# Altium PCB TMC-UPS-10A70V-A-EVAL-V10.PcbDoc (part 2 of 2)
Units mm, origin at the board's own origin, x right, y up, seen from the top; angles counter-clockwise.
Board outline 85 x 55 mm, 4 copper layers (Top Layer, Mid1, Mid2, Bottom Layer), stack 1.572 mm thick; 131 components, 65 nets, 443 pads, 731 vias.
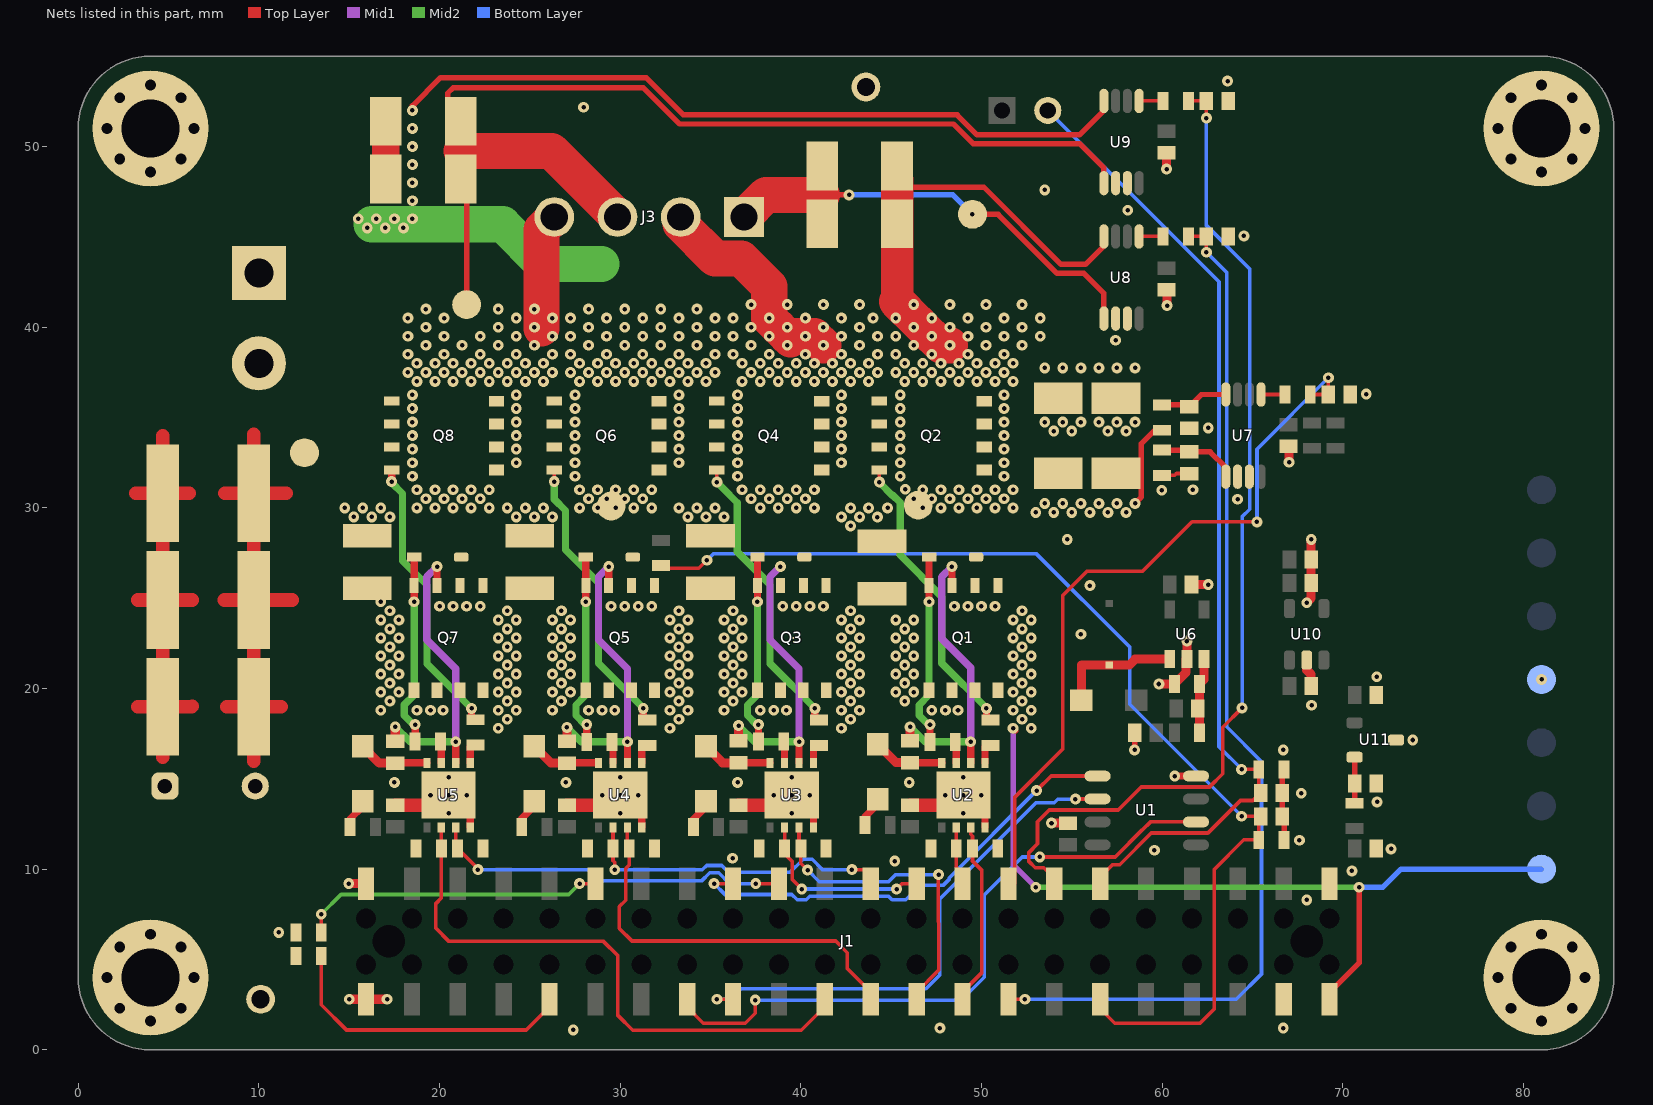
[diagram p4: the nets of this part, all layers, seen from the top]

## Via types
v1: diameter 0.6, hole 0.25, Top Layer to Bottom Layer, tented both sides, 699 vias
v2: diameter 1, hole 0.6, Top Layer to Bottom Layer, tented both sides, 32 vias

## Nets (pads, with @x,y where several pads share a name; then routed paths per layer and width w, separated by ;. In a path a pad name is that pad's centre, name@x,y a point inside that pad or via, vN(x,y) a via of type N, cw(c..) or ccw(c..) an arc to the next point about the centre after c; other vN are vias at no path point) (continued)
GND: C1.1 C2.1 C3.1 C4.1 C5.1 C10.1 C12.1 C13.1 C14.1 C15.1 C16.1 C21.1 C22.1 C23.1 C24.1 C25.1 C26.1 C27.2 C28.1 C29.1 C30.1 C31.1 C32.1 C33.1 C34.1 C35.1 C36.1 J1.2 J1.3 J1.43 J1.44 J2.1 MP1.1 MP2.1 MP3.1 MP4.1 R1.1 R2.1 R3.1 R4.1 R8.1 R9.1 R13.1 R14.1 R18.1 R19.1 R24.1 R25.1 R26.1 R28.1 R31.1 R32.1 TP_GND1.1 TP_GND2.1 TP_GND3.1 U1.4 U2.4 U2.9 U3.4 U3.9 U4.4 U4.9 U5.4 U5.9 U6.2 U7.2 U7.3 U8.2 U8.3 U9.2 U9.3 U10.2 U11.3 | length 72.6
  Top Layer w0.2: R28.1@60,31.8 60.7,31.8 60.8,31.9 C22.1@61.5,31.9
  Top Layer w0.3: v1(20.5,14.1) U5.9@21.7,12.9 ; v1(30,14.1) U4.9@31.2,12.9 ; v1(39.5,14.1) U3.9@40.7,12.9 ; v1(49,14.1) U2.9@50.2,12.9 ; v1(58.475,16.6) C12.1@58.475,17.55 ; R31.1@66.75,11.625 66.75,12.825 C25.1@66.65,12.925 C26.1@66.65,14.225 66.65,15.425 R32.1@66.75,15.525
  Top Layer w0.4: U5.4@21.7,12.315 U5.9@21.7,12.9 ; U4.4@31.2,12.315 U4.9@31.2,12.9 ; U3.4@40.7,12.315 U3.9@40.7,12.9 ; U2.4@50.2,12.315 U2.9@50.2,12.9 ; v1(60.7,15.155) U1.4@61.875,15.155
  Top Layer w0.5: v1(14.975,9.2) J1.44@15.93,9.2 ; v1(15,2.8) v1(17.1,2.8) ; v1(53.875,12.55) C5.1@54.8,12.55 ; v1(59.825,20.25) R24.1@60.675,20.25 61.325,20.9 61.325,21.625 U6.2@61.375,21.625 v1(61.375,22.625) ; C29.1@60.15,49.65 C29.1@60.25,49.65 v1(60.25,48.75) ; v1(60.275,41.2) C27.2@60.275,42.05 ; C10.1@61.625,25.75 v1(62.55,25.75) ; C23.1@67,33.4 67.025,33.375 v1(67.025,32.525) ; U10.2@68,21.575 68,21.025 68.25,20.775 C31.1@68.25,20.15 ; v1(68,24.75) 68.25,25 C32.1@68.25,25.85 C33.1@68.25,27.15 v1(68.25,28.25)
  Top Layer w0.75: 3.175,30.8 C2.1@4.675,30.8 ; 3.3,19 C4.1@4.675,19 ; 3.3,24.9 C3.1@4.675,24.9 ; 4.675,16.2 C4.1@4.675,19 ; 4.675,34 C2.1@4.675,30.8 ; 6.15,30.8 C2.1@4.675,30.8 ; 6.3,19.025 6.275,19 C4.1@4.675,19 ; 6.3,24.9 C3.1@4.675,24.9 ; C16.1@17.55,13.55 19.95,13.55 v1(20.5,14.1) ; C15.1@27.05,13.55 29.45,13.55 v1(30,14.1) ; C14.1@36.55,13.55 38.95,13.55 v1(39.5,14.1) ; C13.1@46.05,13.55 48.45,13.55 v1(49,14.1) ; C4.1@4.675,19 C3.1@4.675,24.9 ; C3.1@4.675,24.9 C2.1@4.675,30.8
  other v1: 27.4,1.1 47.7,1.2 66.7,1.2 11.1,6.5 68,8.3 70.5,9.9 45.2,10.45 36.225,10.6 59.575,11.05 72.675,11.125 67.6,11.6 20.5,13.1 30,13.1 39.5,13.1 49,13.1 71.9,13.725 19.5,14.1 21.5,14.1 29,14.1 31,14.1 38.5,14.1 40.5,14.1 48,14.1 50,14.1 67.7,14.2 17.5,14.8 27,14.8 36.5,14.8 46,14.8 20.5,15.1 30,15.1 39.5,15.1 49,15.1 66.7,16.6 73.875,17.15 68.275,19.075 81,20.5 71.875,20.65 55.5,23 56,25.7 54.75,28.25 64.175,30.475 59.975,30.975 61.7,31 54,34.25 55,34.25 57,34.25 58,34.25 62.55,34.425 53.5,34.75 54.5,34.75 55.5,34.75 56.5,34.75 57.5,34.75 58.5,34.75 71.3,36.3 53.5,37.75 54.5,37.75 55.5,37.75 56.5,37.75 57.5,37.75 58.5,37.75 57.425,39.275 64.525,45.05 58.1,46.475 53.5,47.6 27.975,52.175 63.625,53.625
  other v2: 4,1.6 81,1.6 2.303,2.303 5.697,2.303 79.303,2.303 82.697,2.303 1.6,4 6.4,4 78.6,4 83.4,4 2.303,5.697 5.697,5.697 79.303,5.697 82.697,5.697 4,6.4 81,6.4 4,48.6 81,48.6 2.303,49.303 5.697,49.303 79.303,49.303 82.697,49.303 1.6,51 6.4,51 78.6,51 83.4,51 2.303,52.697 5.697,52.697 79.303,52.697 82.697,52.697 4,53.4 81,53.4
I_SUM: C17.1 C18.1 C19.1 C20.1 Q2.1 Q2.2 Q2.3 Q4.1 Q4.2 Q4.3 Q6.1 Q6.2 Q6.3 Q8.1 Q8.2 Q8.3 R25.2 R26.2 R27.1 | length 4.9
  Top Layer w0.3: v1(58.5,30.25) 58.85,30.6 58.85,33.55 59.6,34.3 R27.1@60,34.3
  other v1: 42.75,29 44.242,29.492 15.25,29.5 16.25,29.5 17.25,29.5 24.25,29.5 25.25,29.5 26.25,29.5 33.75,29.5 34.75,29.5 35.75,29.5 42.25,29.5 43.25,29.5 53,29.75 54,29.75 55,29.75 56,29.75 57,29.75 58,29.75 14.75,30 15.75,30 16.75,30 23.75,30 24.75,30 25.75,30 33.25,30 34.25,30 35.25,30 42.75,30 43.75,30 44.8,30 53.5,30.25 54.5,30.25 55.5,30.25 56.5,30.25 57.5,30.25
NetC6_1: C6.1 D1.1 U2.8 | length 4
  Top Layer w0.4: C6.1@46.05,15.9 46.065,15.885 U2.8@47.8,15.885
  Top Layer w0.5: D1.1@44.25,16.925 45.275,15.9 C6.1@46.05,15.9
NetC6_2: C6.2 D6.2 Q1.1 Q1.2 Q1.3 Q2.5 Q2.6 Q2.7 Q2.8 Q2.9 R35.2 R36.2 TP6.1 U2.6 U8.8 | length 43.1
  Top Layer w0.3: R36.2@45.325,48.925 45.325,48.175 45.75,47.75 50.125,47.75 54.4,43.475 55.75,43.475 56.775,44.5 U8.8@56.775,45.025
  Top Layer w0.4: Q1.3@48.365,25.7 v1(48.365,26.75) ; U2.6@49.4,15.885 v1(49.4,17.05)
  Top Layer w0.5: C6.2@46.05,17.1 v1(46.05,17.875)
  Top Layer w1.8: 45.325,41.425 R35.2@45.325,45.725 R36.2@45.325,48.175
  Top Layer w2: 45.325,41.425 46.5,40.25 v1(47.25,39.5) 47.75,39 v1(48.25,39)
  Mid1 w0.4: v1(48.365,26.75) 47.795,26.18 47.795,22.75 49.4,21.145 v1(49.4,17.05)
  Mid2 w0.4: v1(46.05,17.875) 46.875,17.05 v1(49.4,17.05)
  other v1: 46.75,30 47.75,30 48.75,30 49.75,30 50.75,30 51.75,30 46.25,30.5 47.25,30.5 48.25,30.5 49.25,30.5 50.25,30.5 51.25,30.5 46.75,31 47.75,31 48.75,31 49.75,31 50.75,31 51.75,31 45.777,31.027 45.5,31.75 51.25,31.75 45.5,32.5 51.25,32.5 45.5,33.25 51.25,33.25 45.5,34 51.25,34 45.5,34.75 51.25,34.75 45.5,35.5 51.25,35.5 45.5,36.25 51.25,36.25 45.75,37 46.75,37 47.75,37 48.75,37 49.75,37 50.75,37 51.75,37 45.25,37.5 46.25,37.5 47.25,37.5 48.25,37.5 49.25,37.5 50.25,37.5 51.25,37.5 45.75,38 46.75,38 47.75,38 48.75,38 49.75,38 50.75,38 51.75,38 45.25,38.5 47.25,38.5 49.25,38.5 51.25,38.5 46.25,39 50.25,39 52.25,39 45.25,39.5 49.25,39.5 51.25,39.5 53.25,39.5 46.25,40 48.25,40 50.25,40 52.25,40 45.25,40.5 47.25,40.5 49.25,40.5 51.25,40.5 53.25,40.5 46.25,41.25 48.25,41.25 50.25,41.25 52.25,41.25
NetC7_1: C7.1 D2.1 U3.8 | length 3.9
  Top Layer w0.4: C7.1@36.565,15.885 U3.8@38.3,15.885
  Top Layer w0.5: D2.1@34.75,16.8 35.665,15.885 C7.1@36.565,15.885
NetC7_2: C7.2 D7.2 J3.2 Q3.1 Q3.2 Q3.3 Q4.5 Q4.6 Q4.7 Q4.8 Q4.9 U3.6 | length 28.7
  Top Layer w0.4: U3.6@39.9,15.885 v1(39.9,17.05)
  Top Layer w0.5: C7.2@36.55,17.1 v1(36.55,17.95)
  Top Layer w2: J3.2@33.35,46.1 33.35,45.703 35.253,43.8 36.7,43.8 38.25,42.25 v1(38.25,40.5) 38.75,40 39.25,39.5 39.6,39.5 ; 39.425,39.325 39.6,39.5 ; v1(41.25,39) 40.75,39.5 v1(40.25,39.5) 39.6,39.5
  Mid1 w0.4: v1(38.865,26.75) 38.295,26.18 38.295,22.7 39.9,21.095 v1(39.9,17.05)
  Mid2 w0.4: v1(36.55,17.95) 37.45,17.05 v1(39.9,17.05)
  other v1: 37.75,30 38.75,30 39.75,30 40.75,30 37.25,30.5 38.25,30.5 39.25,30.5 40.25,30.5 36.75,31 37.75,31 38.75,31 39.75,31 40.75,31 36.5,31.75 36.5,32.5 42.25,32.5 36.5,33.25 42.25,33.25 36.5,34 42.25,34 36.5,34.75 42.25,34.75 36.5,35.5 42.25,35.5 36.5,36.25 42.25,36.25 36.75,37 37.75,37 38.75,37 39.75,37 40.75,37 41.75,37 42.75,37 43.75,37 37.25,37.5 38.25,37.5 39.25,37.5 40.25,37.5 41.25,37.5 42.25,37.5 43.25,37.5 44.25,37.5 36.75,38 37.75,38 38.75,38 39.75,38 40.75,38 41.75,38 42.75,38 43.75,38 36.25,38.5 38.25,38.5 40.25,38.5 42.25,38.5 44.25,38.5 37.25,39 39.25,39 43.25,39 36.25,39.5 38.25,39.5 42.25,39.5 44.25,39.5 37.25,40 39.25,40 41.25,40 43.25,40 36.25,40.5 40.25,40.5 42.25,40.5 44,40.5 37.25,41.25 39.25,41.25 41.25,41.25 43.25,41.25
NetC8_1: C8.1 D3.1 U4.8 | length 3.9
  Top Layer w0.2: C8.1@27.05,15.875 C8.1@27.06,15.885
  Top Layer w0.4: C8.1@27.06,15.885 U4.8@28.8,15.885
  Top Layer w0.5: D3.1@25.25,16.8 26.175,15.875 C8.1@27.05,15.875
NetC8_2: C8.2 D8.2 Q5.1 Q5.2 Q5.3 Q6.5 Q6.6 Q6.7 Q6.8 Q6.9 R37.2 R38.2 TP8.1 U4.6 U9.8 | length 75.7
  Top Layer w0.3: v1(18.5,52) 18.5,52.25 20.062,53.812 31.438,53.812 33.5,51.75 48.657,51.75 49.757,50.65 55.425,50.65 56.775,52 U9.8@56.775,52.525
  Top Layer w0.4: Q5.3@29.365,25.7 v1(29.365,26.75) ; U4.6@30.4,15.885 v1(30.4,17.05)
  Top Layer w0.5: C8.2@27.05,17.075 v1(27.05,17.85)
  Top Layer w1.5: R37.2@17.025,48.2 R38.2@17.025,51.4
  Mid1 w0.4: v1(29.365,26.75) 28.795,26.18 28.795,22.7 30.4,21.095 v1(30.4,17.05)
  Mid2 w0.4: v1(27.05,17.85) 27.85,17.05 v1(30.4,17.05)
  Mid2 w2: 16.25,45.7 23.497,45.7 25.697,43.5 28.975,43.5
  other v1: 27.75,30 28.75,30 29.75,30 30.75,30 31.75,30 28.25,30.5 29.25,30.5 30.25,30.5 31.25,30.5 27.75,31 28.75,31 29.75,31 30.75,31 31.75,31 27.5,31.75 27.5,32.5 33.25,32.5 27.5,33.25 33.25,33.25 27.5,34 33.25,34 27.5,34.75 33.25,34.75 27.5,35.5 33.25,35.5 27.5,36.25 33.25,36.25 27.75,37 28.75,37 29.75,37 30.75,37 31.75,37 32.75,37 33.75,37 34.75,37 27.25,37.5 28.25,37.5 29.25,37.5 30.25,37.5 31.25,37.5 32.25,37.5 33.25,37.5 34.25,37.5 35.25,37.5 27.75,38 28.75,38 29.75,38 30.75,38 31.75,38 32.75,38 33.75,38 34.75,38 27.25,38.5 29.25,38.5 31.25,38.5 33.25,38.5 35.25,38.5 28.25,39 30.25,39 32.25,39 34.25,39 27.25,39.5 29.25,39.5 31.25,39.5 33.25,39.5 35.25,39.5 28.25,40 30.25,40 32.25,40 34.25,40 27.25,40.5 29.25,40.5 31.25,40.5 33.25,40.5 35.25,40.5 28.25,41 30.25,41 32.25,41 34.25,41 16,45.5 17,45.5 18,45.5 15.5,46 16.5,46 17.5,46 18.5,46 18.5,47 18.5,48 18.5,49 18.5,50 18.5,51
NetC9_1: C9.1 D4.1 U5.8 | length 3.9
  Top Layer w0.4: C9.1@17.55,15.875 17.56,15.885 U5.8@19.3,15.885
  Top Layer w0.5: D4.1@15.75,16.8 16.675,15.875 C9.1@17.55,15.875
NetC9_2: C9.2 D9.2 J3.4 Q7.1 Q7.2 Q7.3 Q8.5 Q8.6 Q8.7 Q8.8 Q8.9 U5.6 | length 23.8
  Top Layer w0.4: Q7.3@19.865,25.7 v1(19.865,26.75) ; U5.6@20.9,15.885 v1(20.9,17.05)
  Top Layer w0.5: C9.2@17.55,17.075 v1(17.55,17.875)
  Top Layer w2: 25.65,39.925 25.65,40.5 25.65,45.4 J3.4@26.35,46.1
  Mid1 w0.4: v1(19.865,26.75) 19.295,26.18 19.295,22.7 20.9,21.095 v1(20.9,17.05)
  Mid2 w0.4: v1(17.55,17.875) 18.375,17.05 v1(20.9,17.05)
  other v1: 18.75,30 19.75,30 20.75,30 21.75,30 22.75,30 19.25,30.5 20.25,30.5 21.25,30.5 22.25,30.5 18.75,31 19.75,31 20.75,31 21.75,31 22.75,31 18.5,31.75 18.5,32.5 24.25,32.5 18.5,33.25 24.25,33.25 18.5,34 24.25,34 18.5,34.75 24.25,34.75 18.5,35.5 24.25,35.5 18.5,36.25 24.25,36.25 18.75,37 19.75,37 20.75,37 21.75,37 22.75,37 23.75,37 24.75,37 25.75,37 18.25,37.5 19.25,37.5 20.25,37.5 21.25,37.5 22.25,37.5 23.25,37.5 24.25,37.5 25.25,37.5 26.25,37.5 18.75,38 19.75,38 20.75,38 21.75,38 22.75,38 23.75,38 24.75,38 25.75,38 18.25,38.5 20.25,38.5 22.25,38.5 24.25,38.5 26.25,38.5 19.25,39 21.25,39 23.25,39 25.25,39 18.25,39.5 20.25,39.5 22.25,39.5 24.25,39.5 26.25,39.5 19.25,40 23.25,40 25.25,40 18.25,40.5 20.25,40.5 24.25,40.5 26.25,40.5 19.25,41 23.25,41 25.25,41
NetC11_1: C11.1 R23.1 R24.2 U6.3 | length 4.2
  Top Layer w0.5: R23.1@62.075,17.55 R24.2@62.075,20.25 62.325,20.5 U6.3@62.325,21.625
NetC21_2: C21.2 R27.2 U7.8 | length 3.8
  Top Layer w0.2: C21.2@61.4,35.7 C21.2@61.5,35.6
  Top Layer w0.3: R27.2@60,35.7 C21.2@61.4,35.7 ; C21.2@61.5,35.6 62.175,36.275 U7.8@63.525,36.275
NetC22_2: C22.2 R28.2 U7.1 | length 4.4
  Top Layer w0.2: C22.2@61.4,33.2 C22.2@61.5,33.1
  Top Layer w0.3: R28.2@60,33.2 C22.2@61.4,33.2 ; C22.2@61.5,33.1 62.655,33.1 63.525,32.23 U7.1@63.525,31.725
NetC24_2: C24.2 J1.16 R29.2 | length 41
  Top Layer w0.2: J1.16@51.85,9.2 51.85,13.999 54.5,16.649 54.5,25.15 55.85,26.5 58.933,26.5 61.658,29.225 v1(65.25,29.225) ; R29.2@68.2,36.275 C24.2@69.2,36.275 v1(69.2,37.2)
  Bottom Layer w0.2: v1(65.25,29.225) 65.25,33.25 v1(69.2,37.2)
NetC25_2: C25.2 J1.11 R30.1 R31.2 | length 61.2
  Top Layer w0.2: R30.1@32.25,26.8 32.4,26.65 34.35,26.65 v1(34.8,27.1) ; J1.11@56.57,2.8 56.57,2.28 57.375,1.475 62.1,1.475 62.875,2.25 62.875,9.975 64.525,11.625 R31.2@65.35,11.625 65.35,12.825 C25.2@65.45,12.925 v1(64.4,12.925)
  Bottom Layer w0.2: v1(34.8,27.1) 35.15,27.45 53.05,27.45 58.2,22.3 58.2,19.125 v1(64.4,12.925)
NetC26_2: C26.2 J1.12 J4.2 R32.2 | length 54.4
  Top Layer w0.2: J1.12@56.57,9.2 56.57,9.57 57.25,10.25 57.65,10.25 59.4,12 62.534,12 64.334,13.8 65.025,13.8 C26.2@65.45,14.225 65.35,14.325 R32.2@65.35,15.525 v1(64.4,15.525)
  Bottom Layer w0.2: J4.2@53.67,52 63.15,42.52 63.15,16.775 v1(64.4,15.525)
NetC28_2: C28.2 J1.15 R39.2 | length 57.7
  Top Layer w0.2: J1.15@51.49,2.8 v1(52.4,2.8) ; R39.2@61.45,45.025 C28.2@62.45,45.025 v1(62.45,44.15)
  Bottom Layer w0.2: v1(52.4,2.8) 64.1,2.8 65.5,4.2 65.5,15.95 63.575,17.875 63.575,43.025 v1(62.45,44.15)
NetC30_2: C30.2 J1.14 R40.2 | length 55.7
  Top Layer w0.2: J1.14@54.03,9.2 54.03,9.495 53.45,10.075 52.976,10.075 52.625,10.426 52.625,10.924 53.1,11.399 53.1,12.624 53.751,13.275 57.575,13.275 58.85,14.55 62.625,14.55 63.35,15.275 63.35,17.85 v1(64.425,18.925) ; R40.2@61.45,52.525 C30.2@62.45,52.525 v1(62.45,51.575)
  Bottom Layer w0.2: v1(62.45,51.575) 62.45,45.625 64.85,43.225 64.85,29.925 64.425,29.5 v1(64.425,18.925)
NetC35_2: C35.2 R41.1 U11.2 | length 2.6
  Top Layer w0.3: R41.1@70.65,13.65 C35.2@70.65,14.75 U11.2@70.65,16.2
NetD1_2: D1.2 R5.2 | length 1.7
  Top Layer w0.4: R5.2@43.55,12.45 43.55,12.9 44.25,13.6 D1.2@44.25,13.875
NetD2_2: D2.2 R10.2 | length 1.7
  Top Layer w0.2: D2.2@34.75,13.45 D2.2@34.75,13.75
  Top Layer w0.4: R10.2@34.05,12.325 34.05,12.75 D2.2@34.75,13.45
NetD3_2: D3.2 R15.2 | length 1.7
  Top Layer w0.4: R15.2@24.55,12.325 24.55,12.8 25.275,13.525 D3.2@25.275,13.75
NetD4_2: D4.2 R20.2 | length 1.7
  Top Layer w0.4: R20.2@15.05,12.325 15.05,12.775 15.75,13.475 D4.2@15.75,13.75
NetD5_2: D5.2 L1.2 U6.1 | length 7
  Top Layer w0.5: D5.2@55.525,19.35 55.525,21.275 55.55,21.3 L1.2@57.075,21.3 58.175,21.3 58.5,21.625 U6.1@60.425,21.625
NetD6_1: D6.1 Q1.4 R6.2 | length 10.8
  Top Layer w0.4: v1(47.095,24.8) Q1.4@47.095,25.7 D6.1@47.095,27.275 ; R6.2@47.15,17.05 v1(47.15,18)
  Mid2 w0.4: v1(47.095,24.8) 47.095,19.635 46.55,19.09 46.55,18.51 47.06,18 v1(47.15,18)
NetD7_1: D7.1 Q3.4 R11.2 | length 10.5
  Top Layer w0.2: 37.595,26.97 37.6,26.975
  Top Layer w0.4: v1(37.595,24.8) Q3.4@37.595,25.7 37.595,26.97 ; R11.2@37.65,17.075 v1(37.65,18)
  Mid2 w0.4: v1@37.585,17.975 v1@37.625,17.975 ; v1(37.595,24.8) 37.595,19.635 37.05,19.09 37.05,18.51 37.56,18 v1(37.65,18)
NetD8_1: D8.1 Q5.4 R16.2 | length 10.7
  Top Layer w0.4: v1(28.095,24.8) Q5.4@28.095,25.7 D8.1@28.095,27.225 ; R16.2@28.15,17.05 v1(28.15,18)
  Mid2 w0.4: v1(28.095,24.8) 28.095,19.645 27.825,19.375 27.825,19.365 27.55,19.09 27.55,18.51 28.06,18 v1(28.15,18)
NetD9_1: D9.1 Q7.4 R21.2 | length 10.4
  Top Layer w0.4: v1(18.595,24.8) Q7.4@18.595,25.7 18.595,26.97 18.6,26.975 ; R21.2@18.65,17.075 v1(18.65,18)
  Mid2 w0.4: v1(18.595,24.8) 18.595,19.645 18.05,19.1 18.05,18.51 18.56,18 v1(18.65,18)
NetJ1_17: J1.17 R4.2 U2.3 | length 10.2
  Top Layer w0.2: J1.17@48.95,2.8 48.95,3.2 50.025,4.275 50.025,9.925 49.5,10.45 R4.2@49.5,11.15 49.5,11.825 49.4,11.925 U2.3@49.4,12.315
NetJ1_18: J1.18 R3.2 U2.2 | length 3.3
  Top Layer w0.2: U2.2@48.6,12.315 R3.2@48.6,11.15 48.6,10.1 48.95,9.75 J1.18@48.95,9.2
NetJ1_19: J1.19 R9.2 U3.3 | length 17.6
  Top Layer w0.2: U3.3@39.9,12.315 39.9,11.25 R9.2@40,11.15 40,10.327 v1(40.377,9.95) ; J1.19@46.41,2.8 46.41,3.185 47.625,4.4 v1@47.6,9.7
  Bottom Layer w0.2: v1(40.377,9.95) 41.027,9.3 44.851,9.3 45.251,9.7 v1(47.625,9.7)
NetJ1_20: J1.20 R8.2 U3.2 | length 10.3
  Top Layer w0.2: U3.2@39.1,12.315 R8.2@39.1,11.15 39.1,10.85 39.525,10.425 39.525,9.425 v1(40.05,8.9) ; v1(45.3,8.9) 45.6,9.2 J1.20@46.41,9.2
  Bottom Layer w0.2: v1(40.05,8.9) v1(45.3,8.9)
NetJ1_21: J1.21 R14.2 U4.3 | length 22.4
  Top Layer w0.2: U4.3@30.4,12.315 30.4,11.25 R14.2@30.5,11.15 ; R14.2@30.675,10.975 R14.2@30.5,11.15 ; J1.21@43.87,2.8 43.87,3.205 42.575,4.5 42.575,5.375 41.925,6.025 30.65,6.025 29.955,6.72 29.955,7.93 30.3,8.275 30.3,10.034 30.5,10.234 R14.2@30.5,11.15
NetJ1_22: J1.22 R13.2 U4.2 | length 17.9
  Top Layer w0.2: U4.2@29.6,12.315 R13.2@29.6,11.15 29.6,10.475 29.7,10.375 v1(29.7,9.965) ; v1(42.825,9.975) 43.45,9.975 43.87,9.555 J1.22@43.87,9.2
  Bottom Layer w0.2: v1(29.7,9.965) 34.551,9.965 34.786,10.2 35.614,10.2 35.989,9.825 39.403,9.825 40.128,10.55 40.625,10.55 41.201,9.975 v1(42.825,9.975)
NetJ1_23: J1.23 R18.2 U5.2 | length 32.5
  Top Layer w0.2: U5.2@20.1,12.315 R18.2@20.1,11.15 20.1,8.4 19.8,8.1 19.8,6.725 20.525,6 29.075,6 29.875,5.2 29.875,1.9 30.7,1.075 40.025,1.075 41.33,2.38 J1.23@41.33,2.8
NetJ1_26: J1.26 R19.2 U5.3 | length 20.2
  Top Layer w0.2: U5.3@20.9,12.315 20.9,11.25 R19.2@21,11.15 22.125,10.025 v1(22.125,9.975) ; v1(37.5,9.2) J1.26@38.79,9.2
  Bottom Layer w0.2: v1(22.125,9.975) 28.25,9.975 28.875,9.35 34.501,9.35 34.951,9.8 35.449,9.8 36.049,9.2 v1(37.5,9.2)
NetJ3_1: J3.1 R35.1 R36.1 TP7.1 U8.1 | length 24.1
  Top Layer w0.3: 41.175,47.325 v1(42.675,47.325) ; v1(49.5,46.25) 50.918,46.25 54.193,42.975 55.675,42.975 56.775,41.875 U8.1@56.775,40.475
  Top Layer w2: J3.1@36.85,46.1 38.075,47.325 41.175,47.325
  Bottom Layer w0.3: v1(42.675,47.325) 48.425,47.325 v1(49.5,46.25)
NetJ3_3: J3.3 R37.1 R38.1 TP9.1 U9.1 | length 58.7
  Top Layer w0.3: R38.1@20.45,52.6 20.45,52.95 20.75,53.25 31.293,53.25 33.293,51.25 48.45,51.25 49.55,50.15 55.45,50.15 56.775,48.825 U9.1@56.775,47.975 ; R38.1@21.175,51.4 R38.1@21.175,51.825 ; 21.225,49.75 21.5,49.475 TP9.1@21.5,41.25
  Top Layer w2: 21.225,49.75 26.2,49.75 J3.3@29.85,46.1
NetQ2_4: Q2.4 R7.2 | length 16.3
  Top Layer w0.2: v1(44.35,31.425) Q2.4@44.35,32.095
  Top Layer w0.4: R7.2@50.275,18.25 v1(50.275,18.9)
  Mid2 w0.4: v1(44.35,31.425) 44.35,31.4 45.05,30.7 45.09,30.7 45.5,30.29 45.5,27.385 47.8,25.085 47.8,21.4 v1@50.275,18.925
NetQ4_4: Q4.4 R12.2 | length 16.1
  Top Layer w0.2: v1(35.35,31.425) Q4.4@35.35,32.095
  Top Layer w0.4: R12.2@40.775,18.25 v1(40.775,18.9)
  Mid2 w0.4: v1(35.35,31.425) 36.05,30.725 36.05,30.71 36.46,30.3 36.475,30.3 36.475,27.575 38.3,25.75 38.3,21.375 v1@40.75,18.925
NetQ6_4: Q6.4 R17.2 | length 15.9
  Top Layer w0.2: v1(26.35,31.45) Q6.4@26.35,32.095
  Top Layer w0.4: R17.2@31.275,18.25 v1(31.275,18.9)
  Mid2 w0.4: v1(26.35,31.45) 26.35,30.475 26.975,29.85 26.975,27.675 28.8,25.85 28.8,21.4 v1@31.275,18.925
NetQ8_4: Q8.4 R22.2 | length 15.7
  Top Layer w0.4: v1(17.35,31.45) Q8.4@17.35,32.095 ; R22.2@21.775,18.25 v1(21.775,18.9)
  Mid2 w0.4: v1(17.35,31.45) 17.35,31.39 17.95,30.79 17.95,27.075 19.3,25.725 19.3,21.375 v1(21.775,18.9)
NetR6_1: R6.1 U2.7 | length 1.2
  Top Layer w0.4: R6.1@48.55,17.05 48.6,17 U2.7@48.6,15.885
NetR7_1: R7.1 U2.5 | length 1
  Top Layer w0.3: R7.1@50.2,16.775 R7.1@50.275,16.85
  Top Layer w0.4: U2.5@50.2,15.885 R7.1@50.2,16.775
NetR11_1: R11.1 U3.7 | length 1.1
  Top Layer w0.4: U3.7@39.1,15.885 R11.1@39.1,17.025
NetR12_1: R12.1 U3.5 | length 1
  Top Layer w0.3: R12.1@40.7,16.775 R12.1@40.775,16.85
  Top Layer w0.4: U3.5@40.7,15.885 R12.1@40.7,16.775
NetR16_1: R16.1 U4.7 | length 0.8
  Top Layer w0.4: U4.7@29.6,15.885 R16.1@29.6,16.7
NetR17_1: R17.1 U4.5 | length 1
  Top Layer w0.3: R17.1@31.2,16.775 R17.1@31.275,16.85
  Top Layer w0.4: U4.5@31.2,15.885 R17.1@31.2,16.775
NetR21_1: R21.1 U5.7 | length 1.2
  Top Layer w0.4: U5.7@20.1,15.885 R21.1@20.1,17.075
NetR22_1: R22.1 U5.5 | length 1
  Top Layer w0.3: R22.1@21.7,16.775 R22.1@21.775,16.85
  Top Layer w0.4: U5.5@21.7,15.885 R22.1@21.7,16.775
NetR29_1: R29.1 U7.5 | length 1.3
  Top Layer w0.2: U7.5@65.475,36.275 R29.1@66.8,36.275
NetR39_1: R39.1 U8.5 | length 1.3
  Top Layer w0.2: U8.5@58.725,45.025 R39.1@60.05,45.025
NetR40_1: R40.1 U9.5 | length 1.3
  Top Layer w0.2: U9.5@58.725,52.525 R40.1@60.05,52.525
PWM_H_IDLE: J1.34 R2.2 | length 16.9
  Top Layer w0.2: R2.2@13.45,6.5 v1(13.45,7.5) ; v1(27.75,9.2) J1.34@28.63,9.2
  Mid2 w0.2: v1(13.45,7.5) 14.55,8.6 27.15,8.6 v1(27.75,9.2)
PWM_L_IDLE: J1.35 R1.2 | length 16.9
  Top Layer w0.2: R1.2@13.45,5.2 13.45,2.5 14.85,1.1 24.8,1.1 26.09,2.39 J1.35@26.09,2.8
SPI2_SCK: J1.27 U1.6 | length 29
  Top Layer w0.2: v1(35.35,2.8) J1.27@36.25,2.8 ; v1@55.2,13.885 U1.6@56.425,13.885
  Bottom Layer w0.2: v1(35.35,2.8) 36.125,2.8 36.7,3.375 46.925,3.375 47.7,4.15 47.7,8.361 53.014,13.675 54.025,13.675 54.225,13.875 v1(55.2,13.875)
SPI2_SDI: J1.29 U1.2 | length 36.4
  Top Layer w0.2: J1.29@33.71,2.8 33.71,2.365 34.6,1.475 36.925,1.475 37.475,2.025 v1@37.475,2.475 ; v1(53.225,10.675) 57.4,10.675 58.89,12.165 58.901,12.165 59.351,12.615 U1.2@61.875,12.615
  Bottom Layer w0.2: v1(37.475,2.75) 48.875,2.75 50.15,4.025 50.15,8.575 52.25,10.675 v1(53.225,10.675)
SPI2_SDO: J1.28 U1.5 | length 25.7
  Top Layer w0.2: v1(35.2,9.2) J1.28@36.25,9.2 ; v1(53.05,14.35) 53.855,15.155 U1.5@56.425,15.155
  Bottom Layer w0.2: v1(35.2,9.2) 35.8,8.6 39.501,8.6 39.801,8.3 40.299,8.3 40.499,8.5 44.851,8.5 45.051,8.3 45.8,8.3 46.6,9.1 47.874,9.1 48.225,9.451 48.225,9.525 v1(53.05,14.35)
VM: C1.2 C2.2 C3.2 C4.2 C17.2 C18.2 C19.2 C20.2 J1.1 J2.2 Q1.5 Q1.6 Q1.7 Q1.8 Q1.9 Q3.5 Q3.6 Q3.7 Q3.8 Q3.9 Q5.5 Q5.6 Q5.7 Q5.8 Q5.9 Q7.5 Q7.6 Q7.7 Q7.8 Q7.9 TP1.1 TP4.1 | length 73.1
  Top Layer w0.3: v1(51.75,17.8) v1@51.9,17.65 ; J1.1@69.27,2.8 69.27,3.174 70.9,4.804 v1(70.9,9)
  Top Layer w0.75: 8.075,24.9 C3.2@9.725,24.9 ; 8.125,30.8 C2.2@9.725,30.8 ; 8.225,19 C4.2@9.725,19 ; 9.725,15.975 C4.2@9.725,19 ; 9.725,34.075 C2.2@9.725,30.8 ; 11.225,19 C4.2@9.725,19 ; 11.525,30.8 C2.2@9.725,30.8 ; 11.85,24.9 C3.2@9.725,24.9 ; C4.2@9.725,19 C3.2@9.725,24.9 ; C3.2@9.725,24.9 C2.2@9.725,30.8
  Mid1 w0.3: v1(51.75,17.8) 51.75,10.25 v1(53,9)
  Mid2 w0.3: v1(53,9) v1(70.9,9)
  Bottom Layer w0.3: v1(70.9,9) 72.225,9 73.225,10 TP4.1@81,10
  other v1: 23.25,17.8 32.75,17.8 42.25,17.8 52.75,17.8 23.75,18.3 33.25,18.3 42.75,18.3 52.25,18.3 16.75,18.8 18.75,18.8 19.5,18.8 20.2,18.8 23.25,18.8 24.25,18.8 26.25,18.8 28.25,18.8 29,18.8 29.7,18.8 32.75,18.8 33.75,18.8 35.75,18.8 37.75,18.8 38.5,18.8 39.2,18.8 42.25,18.8 43.25,18.8 47.25,18.8 48,18.8 48.7,18.8 51.75,18.8 52.75,18.8 17.25,19.3 23.75,19.3 26.75,19.3 33.25,19.3 36.25,19.3 42.75,19.3 45.75,19.3 52.25,19.3 16.75,19.8 17.75,19.8 23.25,19.8 24.25,19.8 26.25,19.8 27.25,19.8 32.75,19.8 33.75,19.8 35.75,19.8 36.75,19.8 42.25,19.8 43.25,19.8 45.25,19.8 46.25,19.8 51.75,19.8 52.75,19.8 17.25,20.3 23.75,20.3 26.75,20.3 33.25,20.3 36.25,20.3 42.75,20.3 45.75,20.3 52.25,20.3 16.75,20.8 17.75,20.8 23.25,20.8 24.25,20.8 26.25,20.8 27.25,20.8 32.75,20.8 33.75,20.8 35.75,20.8 36.75,20.8 42.25,20.8 43.25,20.8 45.25,20.8 46.25,20.8 51.75,20.8 52.75,20.8 17.25,21.3 23.75,21.3 26.75,21.3 33.25,21.3 36.25,21.3 42.75,21.3 45.75,21.3 52.25,21.3 16.75,21.8 17.75,21.8 23.25,21.8 24.25,21.8 26.25,21.8 27.25,21.8 32.75,21.8 33.75,21.8 35.75,21.8 36.75,21.8 42.25,21.8 43.25,21.8 45.25,21.8 46.25,21.8 51.75,21.8 52.75,21.8 17.25,22.3 23.75,22.3 26.75,22.3 33.25,22.3 36.25,22.3 42.75,22.3 45.75,22.3 52.25,22.3 16.75,22.8 17.75,22.8 23.25,22.8 24.25,22.8 26.25,22.8 27.25,22.8 32.75,22.8 33.75,22.8 35.75,22.8 36.75,22.8 42.25,22.8 43.25,22.8 45.25,22.8 46.25,22.8 51.75,22.8 52.75,22.8 17.25,23.3 23.75,23.3 26.75,23.3 33.25,23.3 36.25,23.3 42.75,23.3 45.75,23.3 52.25,23.3 16.75,23.8 17.75,23.8 23.25,23.8 24.25,23.8 26.25,23.8 27.25,23.8 32.75,23.8 33.75,23.8 35.75,23.8 36.75,23.8 42.25,23.8 43.25,23.8 45.25,23.8 46.25,23.8 51.75,23.8 52.75,23.8 17.25,24.3 23.75,24.3 26.75,24.3 33.25,24.3 36.25,24.3 42.75,24.3 52.25,24.3 20,24.55 20.75,24.55 21.5,24.55 22.25,24.55 29.5,24.55 30.25,24.55 31,24.55 31.75,24.55 39,24.55 39.75,24.55 40.5,24.55 41.25,24.55 48.5,24.55 49.25,24.55 50,24.55 50.75,24.55 16.75,24.8
pads on no net: J1.0 J1.4 J1.5 J1.8 J1.9 J1.10 J1.13 J1.24 J1.25 J1.30 J1.31 J1.32 J1.33 J1.36 J1.37 J1.38 J1.39 J1.40 J1.41 U7.4 U8.4 U9.4 U10.4

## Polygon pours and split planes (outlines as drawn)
NetC6_2 on Bottom Layer "NetC2_2" (solid, pour order 296): 45,44 54,44 54,28.25 45,28.25
NetC7_2 on Bottom Layer "NetC3_2" (solid, pour order 294): 36,44 44.8,44 44.8,28.25 36,28.25
NetC8_2 on Bottom Layer "NetC4_2" (solid, pour order 292): 27,44 35.8,44 35.8,28.25 27,28.25
NetC9_2 on Bottom Layer "NetC5_2" (solid, pour order 290): 18,28.25 18,44 26.7,44 26.7,40.9 26.7,28.25
GND on Bottom Layer "GND-bot-last" (solid, remove dead copper, pour order 298): 85,0.025 0,0.025 0,55 85,55
VM on Bottom Layer "VM_bot1" (solid, remove dead copper, pour order 288): 55.5,15.75 55.5,28 13.5,28 13.5,40.25 7.25,40.25 7.25,11.5 13.5,11.5 13.5,15.75
GND on Mid2 "GND-mid2-last" (solid, remove dead copper, pour order 286): 85,0 0,0 0,55 85,55
NetC9_2 on Mid2 "NetC5_2" (solid, remove dead copper, pour order 276): 18,26.5 18,44.5 26.7,44.5 26.7,40.9 26.7,26.5
NetC8_2 on Mid2 "NetC4_2" (solid, pour order 278): 27,44.5 35.8,44.5 35.8,26.5 31.3,26.5 27,26.5
NetC7_2 on Mid2 "NetC3_2" (solid, pour order 282): 36,44.5 44.8,44.5 44.8,26.5 36,26.5
NetC6_2 on Mid2 "NetC2_2" (solid, remove dead copper, pour order 284): 45,44.5 54,44.5 54,26.5 45,26.5
NetC8_2 on Mid2 "NetC4_2-Mid2" (solid, pour order 274): 15.25,53.2 15.275,53.175 19.375,53.175 19.375,45.25 19.375,44.7 15.224,44.7
I_SUM on Mid1 "I_SUM_Mid1" (solid, pour order 265): 17.8,30.5 13.75,30.5 13.75,25.4 59,25.4 59,30.5 41.25,30.5 41.25,29.75 35.75,29.75 35.75,30.5 32.25,30.5 32.25,29.75 26.75,29.75 26.75,30.5 23.25,30.5 23.25,29.75 17.8,29.75
GND on Mid1 "GND-mid1-last" (solid, remove dead copper, pour order 271): 84.9,0 -0.1,0 -0.1,55 84.9,55
VM on Mid1 "VM_Mid1" (solid, pour order 266): 54,15.5 54,25.25 13.5,25.25 13.5,40.25 7.25,40.25 7.25,11.5 13.5,11.5 13.5,15.5
NetC9_2 on Mid1 "NetC5_2" (solid, pour order 267): 18,27.5 18,44 26.7,44 26.7,40.9 26.7,27.5
NetC8_2 on Mid1 "NetC4_2" (solid, pour order 268): 27,44 35.8,44 35.8,27.5 32.3,27.5 27,27.5
NetC7_2 on Mid1 "NetC3_2" (solid, pour order 269): 36,44 44.8,44 44.8,27.7 36,27.7
NetC6_2 on Mid1 "NetC2_2" (solid, pour order 270): 54,44 54,39.5 52.5,38 52.5,29.25 45,29.25 45,44
VM on Top Layer "VM_TOP" (solid, pour order 263): 52.25,27.25 52.25,24.796 54.204,24.796 54.25,24.75 54.25,15 13.5,15 13.5,11.5 7.25,11.5 7.25,40.25 14,40.25 14,27.25
I_SUM on Top Layer "I_SUM_Y1" (solid, pour order 256): 23.25,30.5 24.75,32 24.75,35.75 25.5,36.5 26.775,36.5 26.775,32.75 26.75,32.75 26.75,27.5 23.25,27.5
NetC6_2 on Top Layer "OUT_X1" (solid, remove dead copper, pour order 259): 54.25,43.5 54,43.5 50.25,47.25 45,47.249 45,25 52.25,25 54.194,25 54.194,28.694 54.25,28.75 52.25,28.75 52.25,37.75 54.25,39.75
NetC7_2 on Top Layer "OUT_X2" (solid, remove dead copper, pour order 260): 36,31 36.75,30.25 36.75,25 41.75,25 41.75,30.5 44.75,30.5 44.75,50.25 36,50.25
NetC8_2 on Top Layer "OUT_Y1" (solid, pour order 261): 27,25 27,46.5 35.75,46.5 35.75,30.725 32.75,30.725 32.75,25
NetC9_2 on Top Layer "OUT_Y2" (solid, pour order 262): 18,25 18,48.375 26.75,48.375 26.75,30.5 23.25,30.5 23.25,25
GND on Top Layer "GND-top-last" (solid, remove dead copper, pour order 264): 85,0 0,0 0,55 85,55
I_SUM on Top Layer "I_SUM_X2" (solid, pour order 254): 35.775,27.5 36.5,27.5 36.5,30.25 35.795,30.955 35.775,30.955 35.775,36.5 34.5,36.5 33.75,35.75 33.75,32 32.75,31 32.75,27.5
I_SUM on Top Layer "I_SUM_X1" (solid, pour order 253): 44.75,31.75 45.31,31.19 45.31,29.44 46.25,28.5 46.25,27.25 41.75,27.25 41.75,31 42.75,32 42.75,35.75 43.5,36.5 44.775,36.5 44.775,32.75 44.75,32.75
I_SUM on Top Layer "I_SUM_Y2" (solid, pour order 257): 14.25,34.25 15.75,35.75 16.5,36.5 17.775,36.5 17.775,32.75 17.75,32.75 17.75,27.5 14.25,27.5
I_SUM on Top Layer "I_SUM" (solid, pour order 258): 59,29 59,33.25 52.5,33.25 52.5,29
NetC8_2 on Top Layer "NetC4_2-TopSense" (solid, pour order 252): 15.25,53.2 15.275,53.175 19.375,53.175 19.375,45 15.224,45
no net on Top Overlay "line" (solid, pour order 252): 79.825,0 80.625,35.125 81.375,35.125 82.25,-0.075

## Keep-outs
Keep-Out Layer:
  lines w0.5: 0,4 ccw(c4,4) 4,0 ; 0,51 cw(c4,51) 4,55 ; 81,0 ccw(c81,4) 85,4 ; 81,55 cw(c81,51) 85,51 ; 0,0 85,0 85,55 0,55 0,0

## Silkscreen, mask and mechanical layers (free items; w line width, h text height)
Top Overlay:
  drawing of 55 lines, arcs and shapes, not listed
  text "STEPPER" at 46,42.25 h1.2 r180
  text "Y2" at 27.25,40.75 h1.5 r90
  text "3-PHASE" at 46.9,39.4 h1.2 r180
  text "W Y1" at 30.75,38.25 h1.5 r90
  text "U X1" at 37.75,38.25 h1.5 r90
  text "V X2" at 34.05,38.225 h1.5 r90
  text "v1.0" at 83.925,32.65 h1.2 r90
  text "TMC-UPS-10A70V-A-EVAL" at 83.925,6.975 h1.2 r90
Bottom Overlay:
  drawing of 38 lines, arcs and shapes, not listed
  text "Universal Power / Stage 10/70 - EVAL /  / Interface: / Inverter PWM /  / Voltage: / 5...70V /  / Phase Current: / 10A /  / www.trinamic.com" at 54,40 h1.2 r90
PCB Outline:
  the board outline again, w0.05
